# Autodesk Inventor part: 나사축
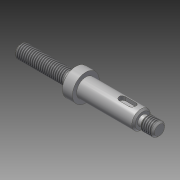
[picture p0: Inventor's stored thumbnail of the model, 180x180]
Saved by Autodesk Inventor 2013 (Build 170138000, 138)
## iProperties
Created: 2019-10
Part Number: 나사축
Material: 강철, 연강
Document SubType Name: Modeling
Designer: mduedu
Density: 1 g/cm^3
Author: mduedu
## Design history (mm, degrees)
revolve "회전1" stored, may be unused: angle "d9" = 90 deg
sketch "스케치2"
  geometry: L1 (0, 4)-(0, -4) reference; L2 (0, -4)-(-33, -4) reference; L3 (-33, -4)-(-33, -8) reference; L4 (-33, -8)-(-39, -8) reference; L5 (-39, -8)-(-39, -5.5) reference; L6 (-39, -5.5)-(-73, -5.5) reference; L7 (-73, -5.5)-(-73, -3) reference; L8 (-76, -4)-(-83, -4) reference; L9 (-83, -4)-(-83, 4) reference; L10 (-83, 4)-(-76, 4) reference; L11 (-73, 3)-(-73, 5.5) reference; L12 (-73, 5.5)-(-39, 5.5) reference; L13 (-39, 5.5)-(-39, 8) reference; L14 (-39, 8)-(-33, 8) reference; L15 (-33, 8)-(-33, 4) reference; L16 (-33, 4)-(0, 4) reference; L17 (0, 0)-(-83, 0); L18 (-31, 3)-(-33, 3); L19 (-33, 3)-(-33, 4); L20 (-31, 3)-(-29.268, 4); L21 (-33, 4)-(-29.268, 4); L22 (-73, -3)-(-75, -3) reference; L23 (-75, -3)-(-76, -4) reference; L24 (-76, 4)-(-75, 3) reference; L25 (-75, 3)-(-73, 3) reference
  constraints: 10 end point, 1 collinear, 1 midpoint, 1 point on line, 1 vertical
  dimensions: "d13" = 1 distance between parallel lines of L18 L21; "d15" = 30 deg angle of L16 L20; "d17" = 2 distance of L18.start L18.end
revolve "회전2" sketch "스케치2" stored, may be unused: angle "d12" = 90 deg
feature "스레드1" dims "d18" = 10, "d19" = 0
feature "스레드2" dims "d20" = 7, "d21" = 0
chamfer "모따기1" distance "d22" = 1; stored, may be unused: second distance "d23" = 2, angle "d24" = 30 deg
chamfer "모따기2" distance "d25" = 1; stored, may be unused: second distance "d26" = 2, angle "d27" = 30 deg
sketch "스케치3"
  geometry: L1 (-31, -3)-(-33, -3) reference; L2 (-33, -3)-(-33, -8) reference; L3 (-33, -8)-(-39, -8) reference; L4 (-39, -8)-(-39, -5.5) reference; L5 (-39, -5.5)-(-72, -5.5) reference; L6 (-72, -5.5)-(-73, -4.5) reference; L7 (-73, -4.5)-(-73, -3) reference; L8 (-76, -4)-(-82, -4) reference; L9 (-82, -4)-(-83, -3) reference; L10 (-83, -3)-(-83, 3) reference; L11 (-83, 3)-(-82, 4) reference; L12 (-82, 4)-(-76, 4) reference; L13 (-73, 3)-(-73, 4.5) reference; L14 (-73, 4.5)-(-72, 5.5) reference; L15 (-72, 5.5)-(-39, 5.5) reference; L16 (-39, 5.5)-(-39, 8) reference; L17 (-39, 8)-(-33, 8) reference; L18 (-33, 8)-(-33, 3) reference; L19 (-33, 3)-(-31, 3) reference; L20 (-31, 3)-(-29.268, 4) reference; L21 (-29.268, 4)-(-1, 4) reference; L22 (-1, 4)-(0, 3) reference; L23 (0, 3)-(0, -3) reference; L24 (0, -3)-(-1, -4) reference; L25 (-1, -4)-(-29.268, -4) reference; L26 (-29.268, -4)-(-31, -3) reference; L27 (-59, 5.5)-(-69, 5.5); L28 (-69, 5.5)-(-69, 3); L29 (-69, 3)-(-59, 3); L30 (-59, 3)-(-59, 5.5); L31 (-73, -3)-(-75, -3) reference; L32 (-75, -3)-(-76, -4) reference; L33 (-76, 4)-(-75, 3) reference; L34 (-75, 3)-(-73, 3) reference; 1 further point
  constraints: 8 end point, 2 parallel, 1 horizontal, 1 perpendicular, 1 point on line
  dimensions: "d28" = 20 distance between parallel lines of L30 L16; "d29" = 10 distance of L27.start L27.end; "d30" = 2.5 distance of L27.end L28.end
extrude "돌출1" cut sketch "스케치3" stored distance "d31" = 4; taper "d32" = 0 deg
fillet "모깎기1"
fillet "모깎기2"
fillet "모깎기3" dims "d36" = 0.6
node "솔리드1"
sketch "스케치1"
  geometry: L1 (0, 0)-(33, 0); L2 (33, 0)-(33, 4); L3 (33, 4)-(0, 4); L4 (0, 4)-(0, 0); L5 (33, 0)-(39, 0); L6 (39, 0)-(39, 8); L7 (39, 8)-(33, 8); L8 (33, 8)-(33, 0); L9 (39, 0)-(73, 0); L10 (73, 0)-(73, 5.5); L11 (73, 5.5)-(39, 5.5); L12 (39, 5.5)-(39, 0); L13 (73, 0)-(83, 0); L14 (83, 0)-(83, 4); L15 (83, 4)-(76, 4); L16 (73, 4)-(73, 0); L17 (73, 3)-(75, 3); L18 (75, 3)-(76, 4)
  constraints: 36 end point, 8 parallel, 5 perpendicular, 4 horizontal, 1 point on line
  dimensions: "d0" = 83 distance between parallel lines of L14 L4; "d2" = 8 diameter of L15 L13; "d3" = 11 diameter of L11 L9; "d4" = 16 diameter of L7 L5; "d5" = 8 diameter of L3 L1; "d6" = 33 distance of L2.end L3.end; "d7" = 6 distance of L6.end L7.end; "d8" = 40 distance between parallel lines of L10 L8; "d33" = 2 distance of L17.start L17.end; "d34" = 135 deg angle of L18 L17; "d35" = 6 diameter of L17 L13 (computed from d2)
node "절단 모서리 투영1"
node "절단 모서리 투영2"
